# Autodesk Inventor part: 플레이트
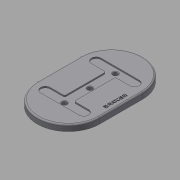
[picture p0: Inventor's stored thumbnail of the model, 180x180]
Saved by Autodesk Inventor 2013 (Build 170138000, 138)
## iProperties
Created: 2016-08
Part Number: 플레이트
Material: 일반
Document SubType Name: Modeling
Designer: mduedu
Density: 2.71 g/cm^3
Author: mduedu
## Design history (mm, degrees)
sketch "스케치1" dims "d0" = 220, "d2" = 130
  geometry: L1 (45, 65)-(-45, 65); L2 (-45, 65)-(-45, -65); L3 (-45, -65)-(45, -65); L4 (45, -65)-(45, 65); L5 (45, 65)-(-45, -65); L6 (-45, 65)-(45, -65); 5 further points
  constraints: 12 end point, 5 midpoint, 2 parallel, 2 vertical alignment, 1 coincident, 1 horizontal, 1 perpendicular, 4 other
extrude "돌출1" new body sketch "스케치1" distance "d3" = 13; taper "d4" = 0 deg
sketch "스케치2"
  geometry: L1 (-63, -50)-(63, -50); L2 (63, -50)-(63, 50); L3 (63, 50)-(-63, 50); L4 (-63, 50)-(-63, -50); L5 (-63, -50)-(63, 50); L6 (63, -50)-(-63, 50); L7 (-63, 50)-(-43, 50); L8 (-43, 50)-(-43, -50); L9 (-43, -50)-(-63, -50); L10 (-63, -50)-(-63, 50); L11 (63, 50)-(43, 50); L12 (43, 50)-(43, -50); L13 (43, -50)-(63, -50); L14 (63, -50)-(63, 50); L15 (-43, -10)-(43, -10); L16 (43, -10)-(43, 10); L17 (43, 10)-(-43, 10); L18 (-43, 10)-(-43, -10); L19 (-43, -10)-(43, 10); L20 (43, -10)-(-43, 10); 1 further point
  constraints: 40 end point, 8 parallel, 4 horizontal, 4 midpoint, 4 perpendicular, 3 point on line
  dimensions: "d18" = 126 distance of L3.end L2.end; "d19" = 100 distance of L2.end L1.end; "d20" = 20 distance of L8.end L9.end; "d21" = 20 distance of L12.end L13.end (= d20); "d22" = 20 distance of L15.end L16.end
extrude "돌출3" cut sketch "스케치2" distance "d23" = 3; taper "d24" = 0 deg
fillet "모깎기2"
fillet "모깎기3"
fillet "모깎기4"
fillet "모깎기5"
fillet "모깎기6" dims "d25" = 3
sketch "스케치4"
  geometry: L1 (-43, -40)-(-43, -13) reference; L2 (-40, -10)-(40, -10) reference; L3 (43, -13)-(43, -40) reference; L4 (63, -40)-(63, 40) reference; L5 (43, 40)-(43, 13) reference; L6 (40, 10)-(-40, 10) reference; L7 (-43, 13)-(-43, 40) reference; L8 (-63, 40)-(-63, -40) reference; L9 (45, -65)-(-45, -65) reference; L10 (-45, 65)-(45, 65) reference; L11 (-53, 40)-(-53, -40); L12 (53, 40)-(53, -40); L13 (-53, 0)-(53, 0); C1 r 5 at (-53, 0); C2 r 5 at (0, 0); C3 r 5 at (53, 0); A1 r 10 centre (-53, -40) between (-63, -40) and (-43, -40) reference; A2 r 3 centre (-40, -13) between (-40, -10) and (-43, -13) reference; A3 r 3 centre (40, -13) between (43, -13) and (40, -10) reference; A4 r 10 centre (53, -40) between (43, -40) and (63, -40) reference; A5 r 10 centre (53, 40) between (63, 40) and (43, 40) reference; A6 r 3 centre (40, 13) between (40, 10) and (43, 13) reference; A7 r 3 centre (-40, 13) between (-43, 13) and (-40, 10) reference; A8 r 10 centre (-53, 40) between (-43, 40) and (-63, 40) reference; A9 r 65 centre (45, 0) between (45, -65) and (45, 65) reference; A10 r 65 centre (-45, 0) between (-45, 65) and (-45, -65) reference; 1 further point
  constraints: 6 end point, 3 centre point, 3 coincident, 2 midpoint, 1 parallel, 1 perpendicular
  dimensions: "d26" = 10 diameter of C1; "d27" = 10 diameter of C2; "d28" = 10 diameter of C3
extrude "돌출4" cut sketch "스케치4" stored distance "d29" = 3; taper "d30" = 0 deg
chamfer "모따기2" distance "d31" = 1; stored, may be unused: second distance "d32" = 2, angle "d33" = 45 deg
fillet "모깎기1" dims "d14" = 3
sketch "스케치3"
  geometry: L1 (-45, -65)-(45, -65) reference; 2 further points
  constraints: 1 vertical alignment, 1 other
  dimensions: "d15" = 12 distance from line of point (0, -53) L1
feature "엠보싱1" sketch "스케치3" dims "d0" = 220, "d2" = 130, "d16" = 0.5, "d17" = 0
node "솔리드1"
node "절단 모서리 투영1"
